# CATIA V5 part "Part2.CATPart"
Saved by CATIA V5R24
Part number: Part2
Bounding box of the stored display mesh (mm): x 0 to 20, y -66.18 to 66.18, z -11.18 to 191.18
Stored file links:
  G:\_CAD수업\DMU_paradoxes\inversion\Part2.CATPart
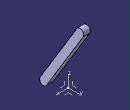
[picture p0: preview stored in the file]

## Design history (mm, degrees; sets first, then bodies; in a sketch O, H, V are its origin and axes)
AxisSystem1: origin (0, 0, 0), X (1, 0, 0), Y (0, 1, 0), Z (0, 0, 1)
Body1 (main body)
  Sketch1 on YZ plane of AxisSystem1, origin (0, 0, 0), H (0, 1, 0), V (0, 0, 1)
    construction line L1 (-55, 0) -> (55, 180)
    line L2 (-64.54, 5.83) -> (45.46, 185.83)
    line L3 (64.54, 174.17) -> (-45.46, -5.83)
    arc A1 centre (55, 180) radius 11.1803 from (45.46, 185.83) to (64.54, 174.17) cw
    arc A2 centre (-55, 0) radius 11.1803 from (-45.46, -5.83) to (-64.54, 5.83) cw
    distance L1 L2 = 11.1803
    tangency: A1 L2, A2 L2, A1 L3, A2 L3
  Pad1: profile Sketch1, direction (1, 0, 0), length 20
